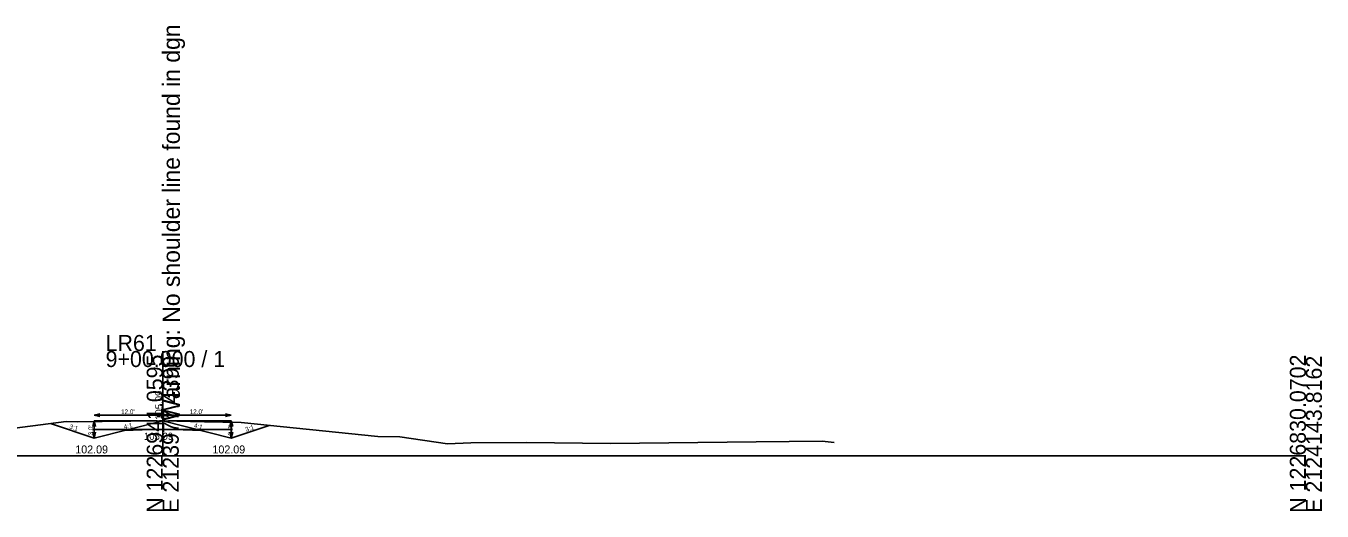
# Model space of a CAD drawing. Extents: x -26 to 1403, y -10 to 9574.
# Drawn here: x 176.1 to 402.8, y 8990.3 to 9075.2 of the extents above; entities that cross this region are included whole.
import ezdxf

# ---------------------------------------------------------------- set-up
doc = ezdxf.new("R2010")
doc.units = 0
for name, color, linetype in [('47', 7, 'Continuous'), ('XS_CELL', 7, 'Continuous'), ('XS_P_FINISHED_GRADE', 7, 'Continuous'), ('XS_P_FINISHED_GRADE_ELEV_TX', 7, 'Continuous'), ('XS_P_SUBGRADE_GRANULAR', 7, 'Continuous'), ('XS_P_TX_CLEARZONE', 7, 'Continuous'), ('XS_P_TX_DCH', 7, 'Continuous'), ('XS_P_TX_FS_BS', 7, 'Continuous'), ('XS_X_GROUND', 7, 'Continuous'), ('XS_X_GROUND_TX', 7, 'Continuous')]:
    doc.layers.add(name, color=color, linetype=linetype)

msp = doc.modelspace()

# ---------------------------------------------------------------- linework, layer by layer
at = {"layer": 'XS_CELL'}
for p, q in [((200, 9000), (200, 9018.31)), ((0, 9000), (200, 9000)), ((200, 9000), (400, 9000))]:
    msp.add_line(p, q, dxfattribs=at)
at = {"layer": 'XS_P_FINISHED_GRADE'}
for p, q in [((188, 9003.09), (180.35, 9005.64)), ((200, 9006.09), (188, 9003.09)), ((200, 9006.09), (212, 9003.09)), ((212, 9003.09), (218.62, 9005.3))]:
    msp.add_line(p, q, dxfattribs=at)
at = {"layer": 'XS_P_SUBGRADE_GRANULAR'}
for p, q in [((187.8, 9004.59), (200, 9004.59)), ((198, 9004.59), (193.24, 9004.4)), ((200, 9004.59), (198, 9004.59)), ((212.2, 9004.59), (200, 9004.59)), ((200, 9004.59), (202, 9004.59)), ((202, 9004.59), (206.76, 9004.4))]:
    msp.add_line(p, q, dxfattribs=at)
at = {"layer": 'XS_P_TX_CLEARZONE'}
for p, q in [((188, 9006.09), (187.75, 9005.09)), ((188, 9007.09), (189, 9007.34)), ((188, 9007.09), (189, 9006.84)), ((200, 9007.09), (188, 9007.09)), ((188, 9006.09), (188.25, 9005.09)), ((188, 9006.09), (188, 9003.09)), ((199, 9006.09), (188, 9006.09)), ((200, 9007.09), (199, 9007.34)), ((200, 9007.09), (199, 9006.84)), ((200, 9007.09), (201, 9007.34)), ((200, 9007.09), (201, 9006.84)), ((200, 9007.09), (212, 9007.09)), ((201, 9006.09), (212, 9006.09)), ((212, 9007.09), (211, 9007.34)), ((212, 9007.09), (211, 9006.84)), ((212, 9006.09), (211.75, 9005.09)), ((212, 9006.09), (212, 9003.09)), ((212, 9006.09), (212.25, 9005.09)), ((188, 9003.09), (187.75, 9004.09)), ((188, 9003.09), (188.25, 9004.09)), ((212, 9003.09), (211.75, 9004.09)), ((212, 9003.09), (212.25, 9004.09))]:
    msp.add_line(p, q, dxfattribs=at)
at = {"layer": 'XS_X_GROUND'}
for p, q in [((169.45, 9004.2), (183.11, 9006)), ((183.11, 9006), (185.12, 9005.9)), ((185.12, 9005.9), (189.42, 9005.97)), ((189.42, 9005.97), (199.44, 9006.1)), ((199.44, 9006.1), (200, 9006.09)), ((200, 9006.09), (207.31, 9005.94)), ((207.31, 9005.94), (213.73, 9005.8)), ((213.73, 9005.8), (237.66, 9003.33)), ((237.66, 9003.33), (241.49, 9003.32)), ((241.49, 9003.32), (249.82, 9002.06)), ((249.82, 9002.06), (253.89, 9002.27)), ((253.89, 9002.27), (263.62, 9002.28)), ((263.62, 9002.28), (278.35, 9002.12)), ((278.35, 9002.12), (303.84, 9002.45)), ((303.84, 9002.45), (315.4, 9002.54)), ((315.4, 9002.54), (317.49, 9002.3))]:
    msp.add_line(p, q, dxfattribs=at)

# ---------------------------------------------------------------- texts
at = {"layer": '47'}
msp.add_text('Warning: No shoulder line found in dgn', height=3, rotation=90, dxfattribs=at).set_placement((203, 9006.09))
msp.add_text('Warning: No shoulder line found in dgn', height=3, rotation=90, dxfattribs=at).set_placement((203, 9006.09))
at = {"layer": 'XS_CELL'}
for s, p in [('LR61', (190, 9018.31)), ('9+00.000 / 1', (190, 9015.51))]:
    msp.add_text(s, height=2.8, dxfattribs=at).set_placement(p)
for s, p in [('N 1226941.0595', (200, 8990)), ('E 2123977.4390', (202.8, 8990)), ('N 1226830.0702', (400, 8990)), ('E 2124143.8162', (402.8, 8990))]:
    msp.add_text(s, height=2.8, rotation=90, dxfattribs=at).set_placement(p)
at = {"layer": 'XS_P_FINISHED_GRADE_ELEV_TX'}
msp.add_text('105.09', height=1.25, rotation=90, dxfattribs=at).set_placement((199.96, 9006.26))
at = {"layer": 'XS_P_TX_CLEARZONE'}
for p in [(192.72, 9007.29), (204.72, 9007.29)]:
    msp.add_text("12.0'", height=0.8, dxfattribs=at).set_placement(p)
for p in [(187.8, 9003.56), (212.2, 9003.56)]:
    msp.add_text("3.0'", height=0.8, rotation=90, dxfattribs=at).set_placement(p)
at = {"layer": 'XS_P_TX_DCH'}
for p in [(184.7, 9000.39), (208.7, 9000.39)]:
    msp.add_text('102.09', height=1.4, dxfattribs=at).set_placement(p)
at = {"layer": 'XS_P_TX_FS_BS'}
for s, rotation, p in [('3:1', 341.5651, (183.59, 9004.77)), ('4:1', 14.0362, (193.29, 9004.62)), ('4:1', 345.9638, (205.39, 9004.95)), ('3:1', 18.4349, (214.6, 9004.17))]:
    msp.add_text(s, height=0.8, rotation=rotation, dxfattribs=at).set_placement(p)
at = {"layer": 'XS_X_GROUND_TX'}
msp.add_text('105.09', height=1.25, rotation=360, dxfattribs=at).set_placement((196.71, 9002.77))

doc.saveas('drawing.dxf')
